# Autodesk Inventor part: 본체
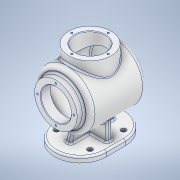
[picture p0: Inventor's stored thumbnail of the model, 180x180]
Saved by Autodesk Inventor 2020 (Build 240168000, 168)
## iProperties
Created: 2023-01
Part Number: 본체
Material: Aluminum 6061
Document SubType Name: Modeling
Designer: home
Density: 2.7 g/cm^3
Appearance: Aluminum - Flat
Mass: 1041.44 g
Surface Area: 1149.73 cm^2
Volume: 385.718 cm^3
Author: home
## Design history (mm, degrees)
sketch "Sketch1"
  geometry: L1 (0, 61)-(0, -61); L2 (38, 61)-(38, 49); L3 (38, 49)-(50, 49); L4 (38, 61)-(27, 61); L5 (27, 61)-(27, 44); L6 (27, 44)-(45, 44); L7 (45, 44)-(45, -45.187); L8 (50, 49)-(50, -49); A1 r 120 centre (-2.354, 58.977) between (0, -61) and (50, -49); A2 r 114.422 centre (-2.354, 58.977) between (0, -55.421) and (45, -45.187); 3 further points
  constraints: 16 end point, 4 point on circle, 4 vertical, 3 perpendicular, 2 centre point, 2 coincident, 2 midpoint, 1 horizontal, 1 horizontal alignment, 1 point on line
  dimensions: "d0" = 122 distance of L1.start L1.end; "d2" = 120 radius of A1; "d3" = 5.57765 radial gap between concentric circles of A1 A2; "d5" = 122 distance from line of L1.end L4; "d7" = 100 diameter of L8 L1; "d8" = 90 diameter of L7 L1; "d9" = 54 diameter of L5 L1; "d10" = 76 diameter of L2 L1; "d11" = 17 distance of L4.end L5.end; "d12" = 110 distance from line of L1.end L3
revolve "Revolution1" sketch "Sketch1" stored, may be unused: angle "d13" = 90 deg
workplane "Work Plane1"
sketch "Sketch2"
  geometry: L1 (0, 63)-(0, -63); L2 (-46.038, 16.963)-(-46.038, -16.962); L3 (46.038, -16.963)-(46.038, 16.962); A1 r 46.038 centre (0, 16.963) between (46.038, 16.962) and (-46.038, 16.963); A2 r 46.038 centre (0, -16.962) between (-46.038, -16.962) and (46.038, -16.963); 2 further points
  constraints: 8 end point, 6 point on circle, 4 tangent, 2 centre point, 2 point on line, 1 coincident, 1 midpoint, 1 parallel, 1 vertical
  dimensions: "d15" = 126 distance of L1.start L1.end; "d16" = 46.0375 radius of A2
extrude "Extrusion1" join sketch "Sketch2" distance "d17" = 10; taper "d18" = 0 deg
workplane "Work Plane3"
  workplane "Work Plane2"
sketch "Sketch3"
  geometry: C1 r 38 at (0, 0); 1 further point
  constraints: 1 centre point, 1 coincident
  dimensions: "d20" = 76 diameter of C1
extrude "Extrusion2" join sketch "Sketch3" stored distance "d21" = 10; taper "d22" = 0 deg
sketch "Sketch4"
  geometry: C1 r 27 at (0, 0); 1 further point
  constraints: 1 centre point, 1 coincident
  dimensions: "d23" = 54 diameter of C1
extrude "Extrusion3" cut sketch "Sketch4" stored distance "d24" = 0; taper "d25" = 0 deg
sketch "Sketch5" dims "d26" = 65
  geometry: 3 further points
  constraints: 1 coincident, 1 horizontal alignment, 2 other
hole "Hole1" sketch "Sketch5" at (-32.5, 0) diameter "d27" = 3.242; stored, may be unused: countersink angle "d31" = 90 deg, drill point angle "d33" = 118 deg; dims "d28" = 8, "d29" = 4, "d30" = 2, "d32" = 10
pattern_circular "Circular Pattern1" dims angle "d35" = 360 deg
sketch "Sketch6" dims "d37" = 65
  geometry: 3 further points
  constraints: 1 coincident, 1 vertical alignment, 2 other
hole "Hole2" sketch "Sketch6" at (0, 32.5) diameter "d38" = 3.242; stored, may be unused: countersink angle "d42" = 90 deg, drill point angle "d44" = 118 deg; dims "d39" = 8, "d40" = 4, "d41" = 2, "d43" = 10
pattern_circular "Circular Pattern2" dims angle "d46" = 360 deg
fillet "Fillet1" dims "d48" = 3
chamfer "Chamfer1" distance "d49" = 1; stored, may be unused: second distance "d50" = 2, angle "d51" = 45 deg
sketch "Sketch7"
  geometry: L1 (46.038, -70)-(-46.038, -70) reference; L2 (-35, -70)-(-35, -35.707); L3 (35, -70)-(35, -35.707); A1 r 50 centre (0, 0) between (-35, -35.707) and (35, -35.707) reference; A2 r 50 centre (0, 0) between (-35, -35.707) and (35, -35.707); 1 further point
  constraints: 4 end point, 4 point on circle, 2 point on line, 2 vertical, 1 centre point, 1 coincident
  dimensions: "d52" = 70 distance between parallel lines of L3 L2; "d53" = 35 distance from line of L3 point (0, 0)
feature "Rib1" sketch "Sketch7" dims "d54" = 1, "d55" = 10, "d56" = 0, "d57" = 0, "d58" = 1, "d59" = 1
sketch "Sketch8"
  geometry: L1 (-70, 16.962)-(-70, 63) reference; L2 (-70, 40)-(-46.143, 33.608); L3 (-46.143, 33.608)-(-46.143, -33.608); L4 (-50, 49)-(-50, -49) reference; L5 (-46.143, -33.608)-(-70, -40); L6 (-70, -63)-(-70, -16.962) reference; 1 further point
  constraints: 6 end point, 2 point on line, 1 parallel
  dimensions: "d60" = 23 distance of L2.start L1.end; "d61" = 80 distance of L5.end L2.start; "d62" = 105 deg angle of L1 L2; "d63" = 105 deg angle of L6 L5
feature "Rib2" sketch "Sketch8" dims "d64" = 1, "d65" = 10, "d66" = 0, "d67" = 0, "d68" = 1, "d69" = 1
fillet "Fillet2" dims "d70" = 8
fillet "Fillet3" dims "d71" = 3
sketch "Sketch9"
  geometry: 5 further points
  constraints: 1 horizontal alignment, 1 vertical alignment
  dimensions: "d72" = 60 distance of point (30, -30) point (-30, -30); "d73" = 30 horizontal distance of point (0, 0) point (-30, -30); "d74" = 60 vertical distance of point (-30.769, 30) point (-30, -30); "d75" = 30 horizontal distance of point (0, 0) point (-30, -30)
hole "Hole3" sketch "Sketch9" at (-30, -30), (-30.769, 30), (30, -30), (30, 30) diameter "d76" = 9; stored, may be unused: countersink angle "d80" = 90 deg, drill point angle "d82" = 0 deg; dims "d77" = 8, "d78" = 4, "d79" = 2, "d81" = 10
fillet "Fillet4" dims "d83" = 3
fillet "Fillet5" dims "d84" = 3
fillet "Fillet6" dims "d85" = 3
chamfer "Chamfer2" distance "d86" = 1; stored, may be unused: second distance "d87" = 2, angle "d88" = 45 deg
body "Solid1"
other parameters: "d19" = 14
